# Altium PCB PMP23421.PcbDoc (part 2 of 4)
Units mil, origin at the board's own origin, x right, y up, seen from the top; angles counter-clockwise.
Board outline 2755.91 x 7559.06 mil, 8 copper layers (Top Layer, Signal Layer 1, Signal Layer 2, Signal Layer 3, Signal Layer 4, Signal Layer 5, Signal Layer 6, Bottom Layer), stack 60.4 mil thick; 211 components, 135 nets, 708 pads, 652 vias.
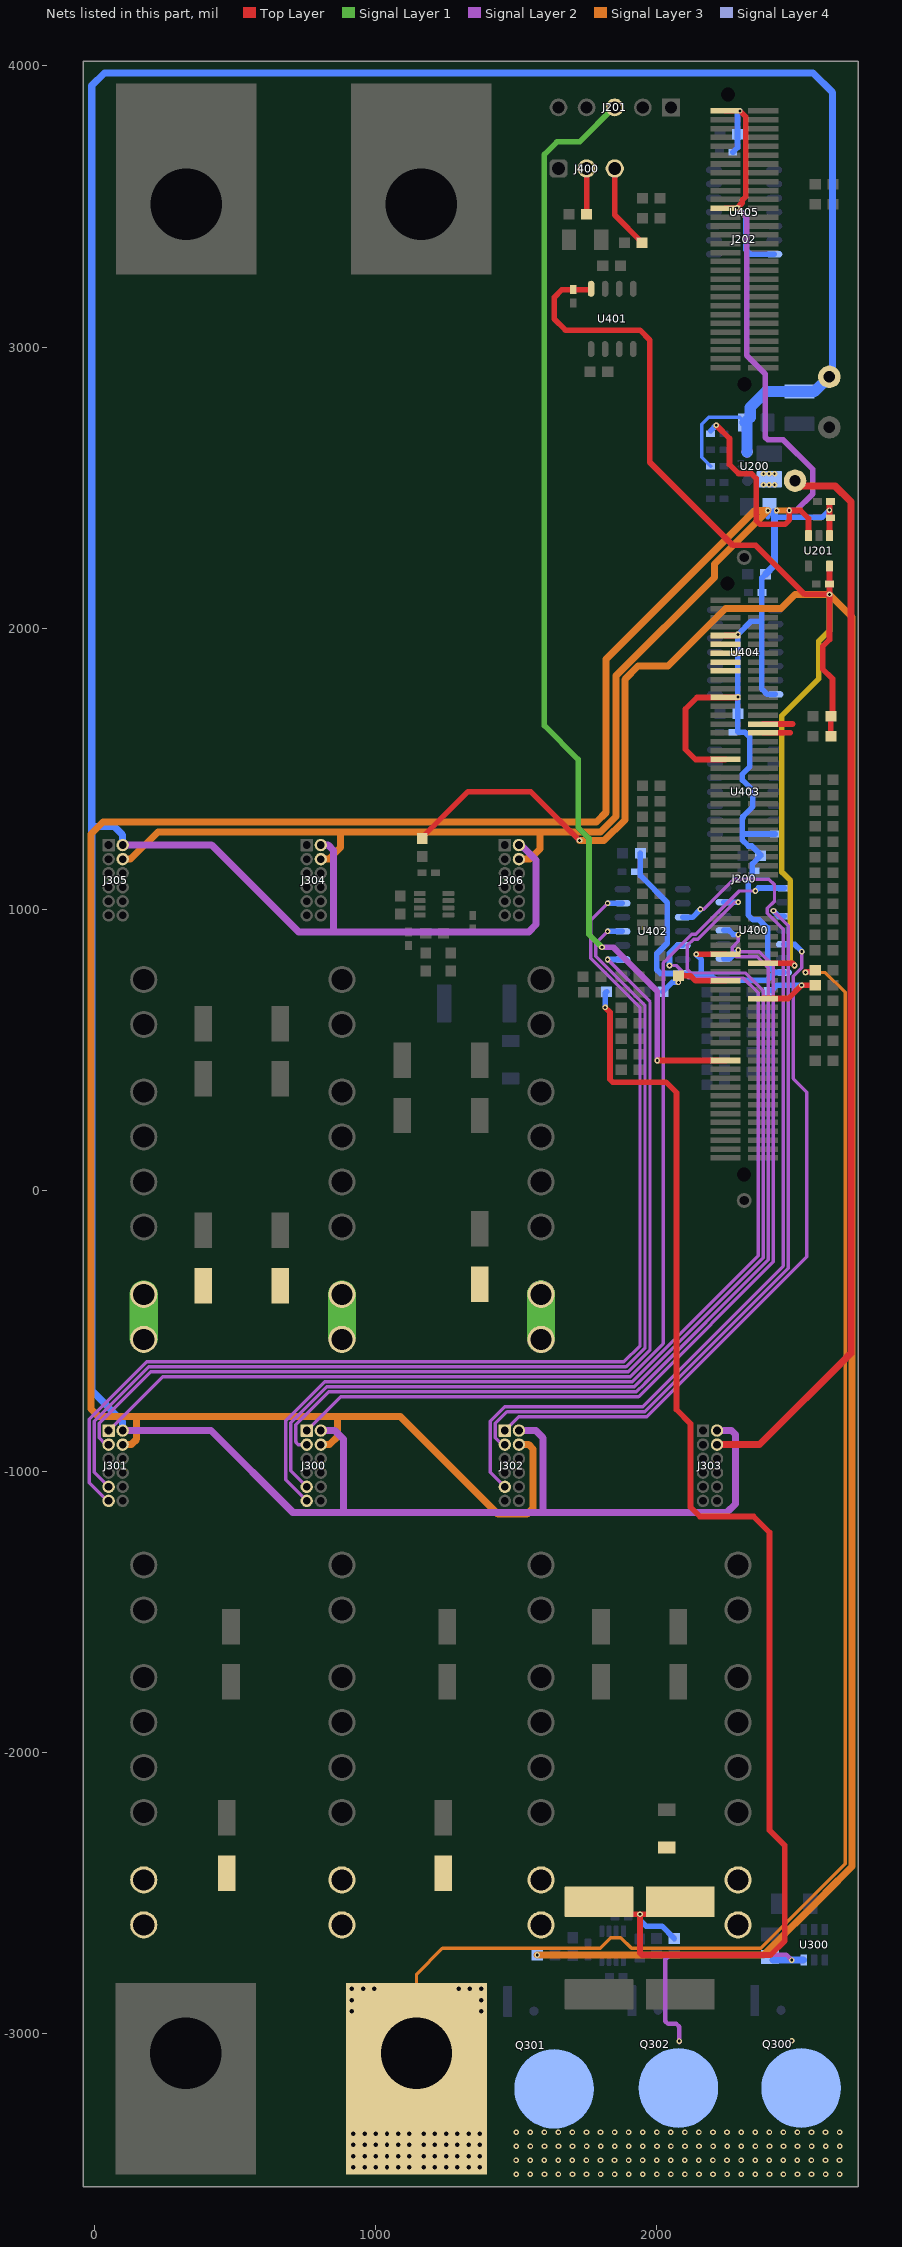
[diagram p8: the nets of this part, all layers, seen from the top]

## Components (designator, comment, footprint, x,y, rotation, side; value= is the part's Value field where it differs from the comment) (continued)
C402 "C1608X7R1C105K080AC" 0603 2337.39,1190.64 r180 bottom value=1uF
C403 "GRM155R70J104KA01D" 0402 2326.28,1137.58 r0 bottom value=0.1uF
C404 "C1608X7R1C105K080AC" 0603 1910,1198.7 r180 bottom value=1uF
C405 "GRM155R70J104KA01D" 0402 1900,1133.99 r0 bottom value=0.1uF
C406 "C1608X7R1C105K080AC" 0603 2257.05,1695.07 r180 bottom value=1uF
C407 "GRM155R70J104KA01D" 0402 2247.05,1630.3 r0 bottom value=0.1uF
C408 "C1608X7R1C105K080AC" 0603 2355,2191.71 r180 bottom value=1uF
C409 "GRM155R70J104KA01D" 0402 2350,2127 r0 bottom value=0.1uF
C410 "C1608X7R1C105K080AC" 0603 2255.56,3757.29 r180 bottom value=1uF
C411 "GRM155R70J104KA01D" 0402 2246.58,3692.58 r0 bottom value=0.1uF
J200 "HSEC8-160-01-L-DV-A-BL" controlCARD-120HSEC 2311.66,1035.21 r90 top locked
J201 "61300511021" Wurth_61300511021 1850.27,3852.41 r180 top
J202 "HSEC8-130-01-L-DV-A" controlCARD-180HSEC-60pinAddon 2311.66,3383.36 r90 top locked
J300 "M50-3000645" FP-M50-3000645_HDR12-MFG 779.72,-979.33 r270 top locked
J301 "M50-3000645" FP-M50-3000645_HDR12-MFG 75,-979.33 r270 top locked
J302 "M50-3000645" FP-M50-3000645_HDR12-MFG 1484.45,-979.33 r270 top locked
J303 "M50-3000645" FP-M50-3000645_HDR12-MFG 2189.17,-979.33 r270 top locked
J304 "M50-3000645" FP-M50-3000645_HDR12-MFG 779.72,1103.35 r270 top locked
J305 "M50-3000645" FP-M50-3000645_HDR12-MFG 75,1103.35 r270 top
J306 "M50-3000645" FP-M50-3000645_HDR12-MFG 1484.45,1103.35 r270 top locked
J400 "61300311121" WURTH_61300311121 1750.27,3635 r0 top
Q300 "IPT010N08NM5ATMA1" FP-IPT010N08NM5ATMA1_HSOF8-MFG 2513.78,-3088.58 r0 bottom
Q301 "IPT010N08NM5ATMA1" FP-IPT010N08NM5ATMA1_HSOF8-MFG 1634.84,-3091.73 r0 bottom
Q302 "IPT010N08NM5ATMA1" FP-IPT010N08NM5ATMA1_HSOF8-MFG 2076.77,-3088.58 r0 bottom
R200 "RC0603JR-070RL" 0603 2595,460.51 r180 top value=0
R201 "CRCW060328K7FKEA" 0603 1769.34,760.67 r180 top value=28.7k
R202 "CRCW060328K7FKEA" 0603 1770.06,705 r180 top value=28.7k
R203 "CRCW060328K7FKEA" 0603 1853.29,707.06 r180 bottom value=28.7k
R204 "CRCW060328K7FKEA" 0603 2595,783.52 r180 top value=28.7k
R205 "RC0603JR-070RL" 0603 2595,532.05 r180 top value=0
R206 "RC0603JR-070RL" 0603 1905,430 r180 top value=0
R207 "RC0603JR-070RL" 0603 1905.51,485 r180 top value=0
R208 "CRCW060328K7FKEA" 0603 1905,760.67 r180 top value=28.7k
R209 "CRCW060328K7FKEA" 0603 1905,705 r180 top value=28.7k
R210 "CRCW060328K7FKEA" 0603 1990.27,707.06 r180 bottom value=28.7k
R211 "CRCW060328K7FKEA" 0603 2595,730 r0 top value=28.7k
R212 "RC0603JR-070RL" 0603 1904.92,595 r180 top value=0
R213 "RC0603JR-070RL" 0603 2595,603.52 r180 top value=0
R214 "CRCW06033K01FKEA" 0603 2210,705.65 r180 bottom value=3.01k
R215 "CRCW06033K01FKEA" 0603 2210,650.65 r180 bottom value=3.01k
R216 "CRCW06033K01FKEA" 0603 2045,763.52 r0 top value=3.01k
R217 "CRCW06033K01FKEA" 0603 2370,705.72 r0 bottom value=3.01k
R218 "RC0603JR-070RL" 0603 2595,675 r180 top value=0
R219 "CRCW040249K9FKED" 0402 2215.07,2576.02 r180 bottom value=49.9k
R220 "RC0402FR-07220KL" 0402 2215.07,2692.04 r180 bottom value=220k
R221 "CRCW040230K0FKED" 0402 2215.07,2634.03 r0 bottom value=30.0k
R222 "CRCW040230K0FKED" 0402 2215.07,2460 r0 bottom value=30.0k
R223 "CRCW06034K75FKEA" 0603 2587.84,1615.72 r0 top value=4.75k
R224 "CRCW06034K75FKEA" 0603 2587.84,1687.2 r0 top value=4.75k
R225 "RC0603JR-070RL" 0603 1606.21,-2720 r0 bottom value=0
R226 "RC0603FR-07100RL" 0603 2030.6,-2661.13 r0 bottom value=100
R227 "RC0603JR-070RL" 0603 1905,540 r0 top value=0
R228 "RC0603FR-07100RL" 0603 2030.6,-2715 r0 bottom value=100
R229 "RC0603JR-070RL" 0603 1165,1220 r270 top value=0
R230 "RC0603FR-07100RL" 0603 1178.11,812.53 r270 top value=100
R231 "RC0603JR-070RL" 0603 1905,650 r0 top value=0
R232 "RC0603FR-07100RL" 0603 1266.69,812.53 r270 top value=100
R300 "CSR2512C0R01F" 2512 1360,665 r0 bottom value=0.01
R301 "PU3921FKNP90U4L" FP-PU3921FKNP90U4L_3921-MFG 2083.34,-2695 r270 top value=400µ
R302 "PU3921FKNP90U4L" FP-PU3921FKNP90U4L_3921-MFG 1794.29,-2695 r270 top value=400µ
R303 "CRCW0805100RDHEAP" 0805_HV 2402.52,-2686.69 r270 bottom value=100
R400 "RCG060310K0FKEA" 0603 2594.9,855 r180 top value=10.0k
R401 "RCG060310K0FKEA" 0603 2594.9,1020 r180 top value=10.0k
R402 "RCG060310K0FKEA" 0603 2594.9,910 r180 top value=10.0k
R403 "RCG060310K0FKEA" 0603 2594.9,1185 r180 top value=10.0k
R404 "RC0603JR-070RL" 0603 1719.13,3473.09 r0 top value=0
R405 "RCG060310K0FKEA" 0603 2594.9,965 r180 top value=10.0k
R406 "RCG060310K0FKEA" 0603 1980,1000 r0 top value=10.0k
R407 "RC0603JR-070RL" 0603 1793.93,2912.57 r0 top value=0
R408 "RC0603FR-07120RL" 0603 1839.21,3289.4 r180 top value=120
R409 "RCG060310K0FKEA" 0603 1980,835 r0 top value=10.0k
R410 "RCG060310K0FKEA" 0603 2594.9,1240 r180 top value=10.0k
R411 "RC0603JR-070RL" 0603 1916.2,3371.66 r0 top value=0
R412 "RCG060310K0FKEA" 0603 2594.9,1075 r180 top value=10.0k
R413 "RCG060310K0FKEA" 0603 1980,945 r0 top value=10.0k
R414 "RCG060310K0FKEA" 0603 2594.9,1130 r180 top value=10.0k
R415 "RCG060310K0FKEA" 0603 1980,890 r0 top value=10.0k
R416 "RCG060310K0FKEA" 0603 1980,1055 r0 top value=10.0k
R417 "RCG060310K0FKEA" 0603 1980,1385 r0 top value=10.0k
R418 "RCG060310K0FKEA" 0603 1980,3458.52 r0 top value=10.0k
R419 "RCG060310K0FKEA" 0603 1980,1110 r0 top value=10.0k
R420 "RCG060310K0FKEA" 0603 1980,1330 r0 top value=10.0k
R421 "RCG060310K0FKEA" 0603 2595,3507.87 r180 top value=10.0k
R422 "RCG060310K0FKEA" 0603 1980,1165 r0 top value=10.0k
R423 "RCG060310K0FKEA" 0603 1980,1275 r0 top value=10.0k
R424 "RCG060310K0FKEA" 0603 1980,3530 r0 top value=10.0k
R425 "RCG060310K0FKEA" 0603 1980,1220 r0 top value=10.0k
R426 "RCG060310K0FKEA" 0603 1980,1440 r0 top value=10.0k
R427 "RCG060310K0FKEA" 0603 2595,3579.35 r180 top value=10.0k
R428 "RCG060310K0FKEA" 0603 2595,1295 r180 top value=10.0k
R429 "RCG060310K0FKEA" 0603 2594.9,1405 r180 top value=10.0k
R430 "RCG060310K0FKEA" 0603 2595,1350 r180 top value=10.0k
R431 "RCG060310K0FKEA" 0603 2595,1460 r180 top value=10.0k
SGND "5001" Keystone5001 2613.78,2714.34 r90 top
T300 "CB70-14-CY" CB70-14-CY 326.77,3507.87 r270 top
T301 "CB70-14-CY" CB70-14-CY 1145.25,-3070 r90 top
T302 "CB70-14-CY" CB70-14-CY 1161.42,3507.87 r270 top
T303 "CB70-14-CY" CB70-14-CY 325,-3070 r90 top
TP300 "Suggest using a net name here" Mill-Max_0312-0-15-15-34-27-10-0 175,-1332.48 r0 top locked
TP301 "Suggest using a net name here" Mill-Max_0312-0-15-15-34-27-10-0 175,-2612.48 r0 top
TP302 "Suggest using a net name here" Mill-Max_0312-0-15-15-34-27-10-0 175,-1892.48 r0 top
TP303 "Suggest using a net name here" Mill-Max_0312-0-15-15-34-27-10-0 879.72,-1332.48 r0 top locked
TP304 "Suggest using a net name here" Mill-Max_0312-0-15-15-34-27-10-0 879.72,-2452.48 r0 top
TP305 "Suggest using a net name here" Mill-Max_0312-0-15-15-34-27-10-0 879.72,-1732.48 r0 top
TP306 "Suggest using a net name here" Mill-Max_0312-0-15-15-34-27-10-0 1588.45,-1332.48 r0 top locked
TP307 "Suggest using a net name here" Mill-Max_0312-0-15-15-34-27-10-0 1588.45,-2612.48 r0 top
TP308 "Suggest using a net name here" Mill-Max_0312-0-15-15-34-27-10-0 1588.45,-1732.48 r0 top
TP309 "Suggest using a net name here" Mill-Max_0312-0-15-15-34-27-10-0 175,-1492.48 r0 top locked
TP310 "Suggest using a net name here" Mill-Max_0312-0-15-15-34-27-10-0 175,-2452.48 r0 top
TP311 "Suggest using a net name here" Mill-Max_0312-0-15-15-34-27-10-0 175,-1732.48 r0 top
TP312 "Suggest using a net name here" Mill-Max_0312-0-15-15-34-27-10-0 879.72,-1492.48 r0 top locked
TP313 "Suggest using a net name here" Mill-Max_0312-0-15-15-34-27-10-0 879.72,-2612.48 r0 top
TP314 "Suggest using a net name here" Mill-Max_0312-0-15-15-34-27-10-0 879.72,-2212.48 r0 top
TP315 "Suggest using a net name here" Mill-Max_0312-0-15-15-34-27-10-0 1588.45,-1492.48 r0 top locked
TP316 "Suggest using a net name here" Mill-Max_0312-0-15-15-34-27-10-0 1588.45,-2452.48 r0 top
TP317 "Suggest using a net name here" Mill-Max_0312-0-15-15-34-27-10-0 1588.45,-2212.48 r0 top
TP318 "Suggest using a net name here" Mill-Max_0312-0-15-15-34-27-10-0 175,-2052.48 r0 top
TP319 "Suggest using a net name here" Mill-Max_0312-0-15-15-34-27-10-0 879.72,-1892.48 r0 top
TP320 "Suggest using a net name here" Mill-Max_0312-0-15-15-34-27-10-0 1588.45,-1892.48 r0 top
TP321 "Suggest using a net name here" Mill-Max_0312-0-15-15-34-27-10-0 175,-2212.48 r0 top
TP322 "Suggest using a net name here" Mill-Max_0312-0-15-15-34-27-10-0 879.72,-2052.48 r0 top
TP323 "Suggest using a net name here" Mill-Max_0312-0-15-15-34-27-10-0 1588.45,-2052.48 r0 top
TP324 "Suggest using a net name here" Mill-Max_0312-0-15-15-34-27-10-0 2289.17,-1332.48 r0 top locked
TP325 "Suggest using a net name here" Mill-Max_0312-0-15-15-34-27-10-0 2289.17,-2612.48 r0 top locked
TP326 "Suggest using a net name here" Mill-Max_0312-0-15-15-34-27-10-0 2289.17,-1732.48 r0 top locked
TP327 "Suggest using a net name here" Mill-Max_0312-0-15-15-34-27-10-0 175,590.2 r0 top locked
TP328 "Suggest using a net name here" Mill-Max_0312-0-15-15-34-27-10-0 175,-529.8 r0 top locked
TP329 "Suggest using a net name here" Mill-Max_0312-0-15-15-34-27-10-0 1588.45,350.2 r0 top locked
TP330 "Suggest using a net name here" Mill-Max_0312-0-15-15-34-27-10-0 879.72,750.2 r0 top
TP331 "Suggest using a net name here" Mill-Max_0312-0-15-15-34-27-10-0 879.72,-529.8 r0 top
TP332 "Suggest using a net name here" Mill-Max_0312-0-15-15-34-27-10-0 879.72,350.2 r0 top
TP333 "Suggest using a net name here" Mill-Max_0312-0-15-15-34-27-10-0 1588.45,590.2 r0 top
TP334 "Suggest using a net name here" Mill-Max_0312-0-15-15-34-27-10-0 1588.45,-529.8 r0 top
TP335 "Suggest using a net name here" Mill-Max_0312-0-15-15-34-27-10-0 175,30.2 r0 top
TP336 "Suggest using a net name here" Mill-Max_0312-0-15-15-34-27-10-0 2289.17,-1492.48 r0 top locked
TP337 "Suggest using a net name here" Mill-Max_0312-0-15-15-34-27-10-0 2289.17,-2452.48 r0 top locked
TP338 "Suggest using a net name here" Mill-Max_0312-0-15-15-34-27-10-0 2289.17,-1892.48 r0 top locked
TP339 "Suggest using a net name here" Mill-Max_0312-0-15-15-34-27-10-0 175,750.2 r0 top locked
TP340 "Suggest using a net name here" Mill-Max_0312-0-15-15-34-27-10-0 175,-369.8 r0 top locked
TP341 "Suggest using a net name here" Mill-Max_0312-0-15-15-34-27-10-0 1588.45,190.2 r0 top locked
TP342 "Suggest using a net name here" Mill-Max_0312-0-15-15-34-27-10-0 879.72,590.2 r0 top
TP343 "Suggest using a net name here" Mill-Max_0312-0-15-15-34-27-10-0 879.72,-369.8 r0 top
TP344 "Suggest using a net name here" Mill-Max_0312-0-15-15-34-27-10-0 879.72,190.2 r0 top
TP345 "Suggest using a net name here" Mill-Max_0312-0-15-15-34-27-10-0 1588.45,750.2 r0 top
TP346 "Suggest using a net name here" Mill-Max_0312-0-15-15-34-27-10-0 1588.45,-369.8 r0 top
TP347 "Suggest using a net name here" Mill-Max_0312-0-15-15-34-27-10-0 175,350.2 r0 top
TP348 "Suggest using a net name here" Mill-Max_0312-0-15-15-34-27-10-0 2289.17,-2052.48 r0 top locked
TP349 "Suggest using a net name here" Mill-Max_0312-0-15-15-34-27-10-0 1588.45,30.2 r0 top locked
TP350 "Suggest using a net name here" Mill-Max_0312-0-15-15-34-27-10-0 879.72,-129.8 r0 top
TP351 "Suggest using a net name here" Mill-Max_0312-0-15-15-34-27-10-0 175,-129.8 r0 top
TP352 "Suggest using a net name here" Mill-Max_0312-0-15-15-34-27-10-0 2289.17,-2212.48 r0 top locked
TP353 "Suggest using a net name here" Mill-Max_0312-0-15-15-34-27-10-0 1588.45,-129.8 r0 top locked
TP354 "Suggest using a net name here" Mill-Max_0312-0-15-15-34-27-10-0 879.72,30.2 r0 top
TP355 "Suggest using a net name here" Mill-Max_0312-0-15-15-34-27-10-0 175,190.2 r0 top
U200 "TPSM863252RDX" RDX0007A-MFG 2373.03,2574.97 r270 bottom
U201 "TLV71333PQDBVRQ1" DBV0005A_N 2576.82,2275 r270 top
U202 "INA296A4IDDF" DDF0008A-MFG 1842.7,-2686.42 r90 bottom
U203 "INA296A3IDDF" DDF0008A-MFG 1207.64,1017.8 r180 top
U300 "LM5050MK-1/NOPB" DDC0006A_N 2560,-2683.77 r270 bottom
U400 "SN74ALS1034D" D0014A_L 2345,925 r0 bottom
U401 "THVD1450D" D0008A_N 1841.18,3100 r90 top
U402 "SN74ALS1034D" D0014A_L 1985,921.41 r0 bottom
U403 "SN74ALS1034D" D0014A_L 2314.41,1417.72 r0 bottom
U404 "SN74ALS1034D" D0014A_L 2314.42,1914.42 r0 bottom
U405 "SN74ALS1034D" D0014A_L 2310.56,3480 r0 bottom

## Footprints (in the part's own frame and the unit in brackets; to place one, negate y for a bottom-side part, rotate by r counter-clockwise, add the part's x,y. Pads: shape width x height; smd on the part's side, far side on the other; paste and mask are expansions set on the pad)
0402 [mm] "0402 from SM-752 data"
  rect 0.8x0.6 smd: 1(-0.6,0) 2(0.6,0)
  silkscreen extent -1.22,-0.52 1.22,0.52, body extent -0.55,-0.3 0.55,0.3, height 0.6
0603 [mm] "0603 from SM-752 data"
  rect 1x0.95 smd: 1(-0.8,0) 2(0.8,0)
  silkscreen extent -1.52,-0.69 1.52,0.69, body extent -0.87,-0.47 0.87,0.47, height 1
0805_HV [mil] "0805 with 30mil clearance between pads"
  rect 50x63 smd: 1(-40,0) 2(40,0)
  silkscreen extent -74,-40 74,40, body extent -43,-29 43,29, height 57
1206 [mm] "1206 from SM-752 data"
  rect 1.3x1.85 smd: 1(-1.45,0) 2(1.45,0)
  silkscreen extent -2.4,-1.21 2.4,1.21, body extent -1.7,-0.9 1.7,0.9, height 1.35
1206_180 [mm] "1206_180"
  rect 1.1x1.6 smd: 1(-1.7,0) 2(1.7,0)
  silkscreen extent -0.9,-1 0.9,1, body extent -1.75,-0.95 1.75,0.95, height 1.8
1210_270 [mm] "1210"
  rect 1.3x2.7 smd: 1(-1.45,0) 2(1.45,0)
  silkscreen extent -2.32,-1.57 2.32,1.57, body extent -1.7,-1.35 1.7,1.35, height 2.7
2512 [mm] "Chip Resistor, Body 6.3x3.2mm, IPC Medium Density"
  rect 1.3x3.4 smd: 1(-2.95,0) 2(2.95,0)
  silkscreen extent -1.9,-1.6 1.9,1.6, body extent -3.22,-1.67 3.22,1.67, height 0.71
CB70-14-CY [mil] "Terminal 90A Lug"
  rect 680x500 hole 254 copper offset -90,0 paste-250: 1(0,0)
  body extent -1300,-260 250,260, height 714
controlCARD-120HSEC [mm] "Pads are not numbered according to Samtec datasheet."
  rect 0.5x2.724 smd: 1(-23.357,-1.678) 2(-23.357,1.722) 3(-22.557,-1.678) 4(-22.557,1.722) 5(-21.757,-1.678) 6(-21.757,1.722) 7(-20.957,-1.678) 8(-20.957,1.722) 9(-20.157,-1.678) 10(-20.157,1.722) 11(-19.357,-1.678) 12(-19.357,1.722) 13(-18.557,-1.678) 14(-18.557,1.722) 15(-17.757,-1.678) 16(-17.757,1.722) 17(-16.957,-1.678) 18(-16.957,1.722) 19(-16.157,-1.678) 20(-16.157,1.722) 21(-15.357,-1.678) 22(-15.357,1.722) 23(-14.557,-1.678) 24(-14.557,1.722) 25(-13.757,-1.678) 26(-13.757,1.722) 27(-12.957,-1.678) 28(-12.957,1.722) 29(-12.157,-1.678) 30(-12.157,1.722) 31(-11.357,-1.678) 32(-11.357,1.722) 33(-10.557,-1.678) 34(-10.557,1.722) 35(-9.757,-1.678) 36(-9.757,1.722) 37(-8.957,-1.678) 38(-8.957,1.722) 39(-8.157,-1.678) 40(-8.157,1.722) 41(-7.357,-1.678) 42(-7.357,1.722) 43(-6.557,-1.678) 44(-6.557,1.722) 45(-5.757,-1.678) 46(-5.757,1.722) 47(-4.957,-1.678) 48(-4.957,1.722) 49(-4.157,-1.678) 50(-4.157,1.722) 51(-3.357,-1.678) 52(-3.357,1.722) 53(-2.557,-1.678) 54(-2.557,1.722) 55(-1.757,-1.678) 56(-1.757,1.722) 57(2.243,-1.678) 58(2.243,1.722) 59(3.043,-1.678) 60(3.043,1.722) 61(3.843,-1.678) 62(3.843,1.722) 63(4.643,-1.678) 64(4.643,1.722) 65(5.443,-1.678) 66(5.443,1.722) 67(6.243,-1.678) 68(6.243,1.722) 69(7.043,-1.678) 70(7.043,1.722) 71(7.843,-1.678) 72(7.843,1.722) 73(8.643,-1.678) 74(8.643,1.722) 75(9.443,-1.678) 76(9.443,1.722) 77(10.243,-1.678) 78(10.243,1.722) 79(11.043,-1.678) 80(11.043,1.722) 81(11.843,-1.678) 82(11.843,1.722) 83(12.643,-1.678) 84(12.643,1.722) 85(13.443,-1.678) 86(13.443,1.722) 87(14.243,-1.678) 88(14.243,1.722) 89(15.043,-1.678) 90(15.043,1.722) 91(15.843,-1.678) 92(15.843,1.722) 93(16.643,-1.678) 94(16.643,1.722) 95(17.443,-1.678) 96(17.443,1.722) 97(18.243,-1.678) 98(18.243,1.722) 99(19.043,-1.678) 100(19.043,1.722) 101(19.843,-1.678) 102(19.843,1.722) 103(20.643,-1.678) 104(20.643,1.722) 105(21.443,-1.678) 106(21.443,1.722) 107(22.243,-1.678) 108(22.243,1.722) 109(23.043,-1.678) 110(23.043,1.722) 111(23.843,-1.678) 112(23.843,1.722) 113(24.643,-1.678) 114(24.643,1.722) 115(25.443,-1.678) 116(25.443,1.722) 117(26.243,-1.678) 118(26.243,1.722) 119(27.043,-1.678) 120(27.043,1.722)
  round 0.025 hole 1.27 unplated mask+0.876: 181(-24.857,0.022) 182(28.543,1.522)
  round 1.348 hole 0.84: 185(-27.207,0.022) 186(30.893,0.022)
  silkscreen extent -32.11,-3.86 35.8,3.9, body extent -31.75,-3.48 35.3,3.52, height 12.35
controlCARD-180HSEC-60pinAddon [mm] "Pads are not numbered according to datasheet."
  round 0.025 hole 1.27 unplated mask+0.876: 61(-13.1,0) 62(13.1,1.5)
  rect 0.5x2.724 smd: 121(-11.6,-1.7) 122(-11.6,1.7) 123(-10.8,-1.7) 124(-10.8,1.7) 125(-10,-1.7) 126(-10,1.7) 127(-9.2,-1.7) 128(-9.2,1.7) 129(-8.4,-1.7) 130(-8.4,1.7) 131(-7.6,-1.7) 132(-7.6,1.7) 133(-6.8,-1.7) 134(-6.8,1.7) 135(-6,-1.7) 136(-6,1.7) 137(-5.2,-1.7) 138(-5.2,1.7) 139(-4.4,-1.7) 140(-4.4,1.7) 141(-3.6,-1.7) 142(-3.6,1.7) 143(-2.8,-1.7) 144(-2.8,1.7) 145(-2,-1.7) 146(-2,1.7) 147(-1.2,-1.7) 148(-1.2,1.7) 149(-0.4,-1.7) 150(-0.4,1.7) 151(0.4,-1.7) 152(0.4,1.7) 153(1.2,-1.7) 154(1.2,1.7) 155(2,-1.7) 156(2,1.7) 157(2.8,-1.7) 158(2.8,1.7) 159(3.6,-1.7) 160(3.6,1.7) 161(4.4,-1.7) 162(4.4,1.7) 163(5.2,-1.7) 164(5.2,1.7) 165(6,-1.7) 166(6,1.7) 167(6.8,-1.7) 168(6.8,1.7) 169(7.6,-1.7) 170(7.6,1.7) 171(8.4,-1.7) 172(8.4,1.7) 173(9.2,-1.7) 174(9.2,1.7) 175(10,-1.7) 176(10,1.7) 177(10.8,-1.7) 178(10.8,1.7) 179(11.6,-1.7) 180(11.6,1.7)
  silkscreen extent -14.68,-3.88 14.68,3.88, body extent -14.3,-3.5 14.3,3.5, height 7.95
D0008A_N [mm] "SOIC, 8-Leads, Body 4.9x3.9mm, Pitch 1.27mm, IPC Medium Density"
  oval 1.45x0.6 smd: 1(-2.725,1.905) 2(-2.725,0.635) 3(-2.725,-0.635) 4(-2.725,-1.905) 5(2.725,-1.905) 6(2.725,-0.635) 7(2.725,0.635) 8(2.725,1.905)
  silkscreen extent -3.3,-2.5 0.9,2.5, body extent -3,-2.45 3,2.45, height 1.63
D0014A_L [mm] "SOIC, 14-Leads, Body 8.7x3.9mm, Pitch 1.27mm, IPC High Density"
  oval 1.45x0.6 smd: 1(-2.725,3.81) 2(-2.725,2.54) 3(-2.725,1.27) 4(-2.725,0) 5(-2.725,-1.27) 6(-2.725,-2.54) 7(-2.725,-3.81) 8(2.725,-3.81) 9(2.725,-2.54) 10(2.725,-1.27) 11(2.725,0) 12(2.725,1.27) 13(2.725,2.54) 14(2.725,3.81)
  silkscreen extent -3.3,-4.4 0.9,4.4, body extent -3.02,-4.32 3.02,4.32, height 1.6
DBV0005A_N [mm] "SOT23, 5-Leads, Body 2.9x1.6mm, Pitch 0.95mm, Lead Span 2.8mm, IPC Medium Density"
  rrect17% 1x0.6 smd: 1(-1.375,0.95) 2(-1.375,0) 3(-1.375,-0.95) 4(1.375,-0.95) 5(1.375,0.95)
  silkscreen extent -1.63,-1.55 0.38,1.55, body extent -1.42,-1.46 1.42,1.46, height 1.09
DDC0006A_N [mm]
  rrect17% 1x0.6 smd: 1(-1.375,0.95) 2(-1.375,0) 3(-1.375,-0.95) 4(1.375,-0.95) 5(1.375,0) 6(1.375,0.95)
  silkscreen extent -1.75,-1.52 0.7,1.53, body extent -1.43,-1.48 1.43,1.49, height 0.92
DDF0008A-MFG [mm]
  rrect22% 1.05x0.45 smd paste+0 mask+0: 1(-1.3,0.975) 2(-1.3,0.325) 3(-1.3,-0.325) 4(-1.3,-0.975) 5(1.3,-0.975) 6(1.3,-0.325) 7(1.3,0.325) 8(1.3,0.975)
  silkscreen extent -2.01,-1.48 0.4,1.67, body extent -1.41,-1.45 1.41,1.45, height 1.1
FP-IPT010N08NM5ATMA1_HSOF8-MFG [mm]
  rrect13% 0.8x2.8 smd paste-1000 mask+0: 1(-4.2,-5.25)
  round 0.837 smd paste-1000 mask+0: 2-3-4-5-6-7-8(-1.825,-4.375)
  round 7.2 smd paste-1000 mask+0: 9(0,2.65)
  Top Layer region: 4.6,-6.65 4.6,-3.85 -3.4,-3.85 -3.4,-6.65 -2.6,-6.65 -2.6,-4.65 -2.2,-4.65 -2.2,-6.65 -1.4,-6.65 -1.4,-4.65 -1,-4.65 -1,-6.65 -0.2,-6.65 -0.2,-4.65 0.2,-4.65 0.2,-6.65 1,-6.65 1,-4.65 1.4,-4.65 1.4,-6.65 2.2,-6.65 2.2,-4.65 2.6,-4.65 2.6,-6.65 3.4,-6.65 3.4,-4.65 3.8,-4.65 3.8,-6.65 4.6,-6.65
  Top Layer region: -5.05,6.65 5.05,6.65 5.05,5.25 4.35,5.25 4.35,2.35 5.05,2.35 5.05,-1.35 -5.05,-1.35 -5.05,2.35 -4.35,2.35 -4.35,5.25 -5.05,5.25 -5.05,6.65
  silkscreen extent -5.05,-7.32 5.05,-1.73, body extent -4.95,-5.84 4.95,5.84, height 2.4
FP-M50-3000645_HDR12-MFG [mm]
  rrect9% 1.12x1.12 hole 0.7 paste-1000 mask+0: 1(-3.175,-0.635)
  round 1.12 hole 0.7 paste-1000 mask+0: 2(-3.175,0.635) 3(-1.905,-0.635) 4(-1.905,0.635) 5(-0.635,-0.635) 6(-0.635,0.635) 7(0.635,-0.635) 8(0.635,0.635) 9(1.905,-0.635) 10(1.905,0.635) 11(3.175,-0.635) 12(3.175,0.635)
  silkscreen extent -4.73,-1.63 4.16,1.63, body extent -4.26,-1.73 4.26,1.73, height 0.25
FP-PU3921FKNP90U4L_3921-MFG [mm]
  rrect4% 2.75x6.2 smd paste+0 mask+0: 1(-4.175,0) 2(4.175,0)
  silkscreen extent -2.42,-2.73 2.42,2.73, body extent -5,-2.6 5,2.6, height 1.81
Keystone5000 [mil] "For Keystone 500x miniature loop terminals"
  round 80 hole 40: 1(0,0)
  silkscreen extent -52,-52 52,52, body extent -49,-49 49,49, height 182
Keystone5001 [mil] "For Keystone 500x miniature loop terminals"
  round 80 hole 40: 1(0,0)
  silkscreen extent -52,-52 52,52, body extent -49,-49 49,49, height 182
Mill-Max_0312-0-15-15-34-27-10-0 [mm] "Pin Receptacle, .032-.046\" .075\" Dia, Gold, TH"
  round 2.45 hole 1.905: 1(0,0)
  silkscreen extent -1.52,-1.52 1.52,1.52, body extent -1.15,-1.15 1.16,1.15, height 0.46
RDX0007A-MFG [mm]
  round 1.025 smd paste-1000 mask-1000: 1(-1.312,1.312)
  rrect13% 1.5x2.3 smd paste-1000 mask-1000: 2(-1.15,-0.675) 3(1.15,-0.675)
  round 0.991 smd paste-1000 mask-1000: 4(1.281,1.276)
  rrect45% 0.22x0.6 smd paste+0 mask-1000: 5(0.5,1.9) 6(0,1.9) 7(-0.5,1.9)
  Top Layer region: 1.9,1.8 1.892,1.838 1.871,1.871 1.838,1.892 1.8,1.9 1.8,1.9 0.925,1.9 0.887,1.892 0.854,1.871 0.833,1.838 0.825,1.8 0.825,1.8 0.825,1.634 0.818,1.596 0.796,1.563 0.796,1.563 0.507,1.274 0.474,1.252 0.436,1.245 0.436,1.245 0.39,1.245 0.352,1.237 0.319,1.216 0.298,1.183 0.29,1.145 0.29,1.145 0.29,0.825 0.298,0.787 0.319,0.754 0.352,0.733 0.39,0.725 0.39,0.725 1.8,0.725 1.838,0.733 1.871,0.754 1.892,0.787 1.9,0.825 1.9,0.825
  Top Layer region: -1.9,1.8 -1.887,1.85 -1.85,1.887 -1.8,1.9 -1.8,1.9 -0.925,1.9 -0.887,1.892 -0.854,1.871 -0.833,1.838 -0.825,1.8 -0.825,1.8 -0.825,1.634 -0.818,1.596 -0.796,1.563 -0.796,1.563 -0.507,1.274 -0.474,1.252 -0.436,1.245 -0.436,1.245 -0.39,1.245 -0.34,1.232 -0.303,1.195 -0.29,1.145 -0.29,1.145 -0.29,0.825 -0.298,0.787 -0.319,0.754 -0.352,0.733 -0.39,0.725 -0.39,0.725 -1.8,0.725 -1.838,0.733 -1.871,0.754 -1.892,0.787 -1.9,0.825 -1.9,0.825
  Keep-Out Layer region: -0.2,1.295 0.2,1.295 0.2,0.675 -0.2,0.675
  silkscreen extent -2.52,-2.17 2.07,2.37, body extent -1.65,-2 1.65,2, height 2.1
SM_RADIAL_D [mm] "6.3 x 5.8mm:  Panasonic D"
  rect 3.2x1.6 smd: 1(-2.5,0) 2(2.5,0)
  silkscreen extent -3.4,-3.4 3.4,3.4, body extent -3.4,-3.4 3.4,3.4, height 6.1
WURTH_61300311121 [mm] "Header, 2.54mm, 3x1, TH"
  rrect50% 1.65x1.65 hole 1.15: 1(-2.54,0)
  round 1.65 hole 1.15: 2(0,0) 3(2.54,0)
  body extent -3.81,-1.27 3.81,1.27, height 8.54
Wurth_61300511021 [mm] "Header, 2.54 mm, 5x1, R/A, TH"
  rect 1.6x1.6 hole 1.1: 1(-5.08,0)
  round 1.6 hole 1.1: 2(-2.54,0) 3(0,0) 4(2.54,0) 5(5.08,0)
  silkscreen extent -6.75,-4.04 6.35,-1.5, body extent -6.35,-10.04 6.35,0.32, height 2.55

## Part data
5V 12Vs: "Test Point, Miniature, Red, TH", Color=Red, Manufacturer=Keystone, Supplier Part Number 1=36-5000-ND
C200 C201 C202 C203 C204 C205 C206 C219 C225: "CAP, CERM, 10 pF, 50 V,+/- 1%, C0G/NP0, 0603", Cap_Case=0603, Manufacturer=Kemet, Supplier Part Number 1=399-9958-1-ND, TempCo=C0G/NP0, Tolerance_%=1, Value2=50V, ValueDisplayed=10pF
C207: library part CMP-0009211-2, "CAP, CERM, 47 uF, 16 V, +/- 10%, X5R, 1210", Cap_Case=1210, Manufacturer=MuRata, Supplier Part Number 1=GRM32ER61C476KE15L-ND, TempCo=X5R, Tolerance_%=10%, Value1=Unknown, Value2=16V, ValueDisplayed=47uF
C208: library part CMP-0007728-2, "CAP, CERM, 1 uF, 25 V, +/- 10%, X7R, 0805", Cap_Case=0805, Manufacturer=Kemet, Supplier Part Number 1=399-8004-1-ND, TempCo=X7R, Tolerance_%=10%, Value1=Unknown, Value2=25V, ValueDisplayed=1uF
C209: library part CMP-0007989-2, "CAP, CERM, 22 uF, 6.3 V, +/- 10%, X5R, 0805", Cap_Case=0805, Manufacturer="Samsung Electro-Mechanics", TempCo=X5R, Tolerance_%=10%, Value1=Unknown, Value2=6.3V, ValueDisplayed=22uF
C210 C212 C213 C218 C224 C400 C403 C405 C407 C409 C411: "CAP, CERM, 0.1uF, 6.3V, +/-10%, X7R, 0402", Cap_Case=0402, Manufacturer=MuRata, Supplier Part Number 1=GRM155R70J104KA01D-ND, TempCo=X7R, Tolerance_%=10, Value1=Unknown, Value2=6.3V, ValueDisplayed=0.1uF
C211: library part CMP-0078218-1, "CAP, CERM, 0.01 µF, 16 V,+/- 10%, X7R, 0402", Cap_Case=0402, Manufacturer=Kemet, Supplier Part Number 1=399-1038-1-ND, TempCo=X7R, Tolerance_%=10%, Value2=16V, ValueDisplayed=0.01µF
C214 C220: "CAP, CERM, 68 pF, 50 V,+/- 5%, C0G/NP0, 0603", Cap_Case=0603, Manufacturer=AVX, Supplier Part Number 1=478-1173-1-ND, TempCo=C0G/NP0, Tolerance_%=5, Value1="0.144 ohm", Value2=50V, ValueDisplayed=68pF
C215 C216 C221 C222: "CAP, CERM, 47 pF, 50 V,+/- 1%, C0G/NP0, 0402", Cap_Case=0402, Manufacturer=MuRata, Supplier Part Number 1=490-6241-1-ND, TempCo=C0G/NP0, Tolerance_%=1, Value2=50V, ValueDisplayed=47pF
C217 C223 C402 C404 C406 C408 C410: "CAP, CERM, 1 µF, 16 V,+/- 10%, X7R, 0603", Cap_Case=0603, Manufacturer=TDK, Supplier Part Number 1=445-1604-1-ND, TempCo=X7R, Tolerance_%=10, Value1="0.0057 ohm", Value2=16V, ValueDisplayed=1µF
C300 C313: library part C3216X6S1H475K160AB, "CAP CER 4.7UF 100V X7S 1206", Cap_Case=1206, TempCo=X7S, Tolerance_%=10, Value2=100V, ValueDisplayed=4.7µF
C301 C302 C303 C304 C305 C306 C307 C308 C309 C310 C311 C312 C315: library part EEE-FK1H220P, "CAP ALUM POLY HYB 22UF 63V SMD", Cap_Case=D, Manufacturer=Rubycon, Tolerance_%=20, Value1="0.88 ohm", Value2=63V, ValueDisplayed=22µF
C314 C401: "CAP, CERM, 0.1 µF, 100 V,+/- 5%, X7R, 1206", Cap_Case=1206, Manufacturer=AVX, Supplier Part Number 1=478-3785-1-ND, TempCo=X7R, Tolerance_%=5, Value1="0.037 ohm", Value2=100V, ValueDisplayed=0.1µF
J200: library part CMP-0003814-2, "C2000 controlCARD-120HSEC connector, SMT", Manufacturer=Samtec
J201: library part CMP-0054800-1, "Header, 2.54 mm, 5x1, Gold, R/A, TH", Color=Black, Manufacturer="Wurth Elektronik", Supplier Part Number 1=732-5338-ND
J202: library part CMP-0003859-2, "C2000 controlCARD-180HSEC (60-pin addon) connector, SMT", Manufacturer=Samtec
J300 J301 J302 J303 J304 J305 J306: library part CMP-0094055-1, "12 Position Receptacle Connector 0.050\" (1.27mm) Through Hole Gold", Current_A=1A, Digikey Part Number=952-1366-5-ND, Manufacturer=Harwin, Mouser Part Number=855-M50-3000645, Operating Temperature Range="-40°C to +105°C"
J400: library part CMP-0054796-4, "Header, 2.54 mm, 3x1, Gold, TH", Manufacturer="Wurth Elektronik", Supplier Part Number 1=732-5316-ND
Q300 Q301 Q302: library part CMP-0120006-1, "Transistor Power MOSFET N-Channel 80V 425A 8-Pin HSOF T/R", Digikey Part Number=448-IPT010N08NM5ATMA1CT-ND, Drain To Source Breakdown Voltage=80V, Input Capacitace At Vds="12000pF @ 40V", Manufacturer=Infineon, Mouser Part Number=726-IPT010N08NM5ATM1, Operating Temperature Range="-55°C to +175°C", Power_W=3.8W, Pulse Drain Current=1700A, Typ Forward Diode Voltage=0.87V
R200 R205 R206 R207 R212 R213 R218 R225 R227 R229 R231 R404 R407 R411: "RES, 0, 5%, 0.1 W, 0603", Manufacturer="Yageo America", Power_W=0.1, Supplier Part Number 1=311-0.0GRCT-ND, TempCo="200 ppm/C", Tolerance_%=5, Value1=5%, Value2=0.1W, Value_Code=0000, ValueDisplayed=0
R201 R202 R203 R204 R208 R209 R210 R211: "RES, 28.7 k, 1%, 0.1 W, 0603", Manufacturer=Vishay-Dale, Power_W=0.1, Supplier Part Number 1=541-28.7KHCT-ND, TempCo="100 ppm/C", Tolerance_%=1, Value1=1%, Value2=0.1W, Value_Code=28k7, ValueDisplayed=28.7k
R214 R215 R216 R217: "RES, 3.01 k, 1%, 0.1 W, 0603", Manufacturer=Vishay-Dale, Power_W=0.1, Supplier Part Number 1=541-3.01KHCT-ND, TempCo="100 ppm/C", Tolerance_%=1, Value1=1%, Value2=0.1W, Value_Code=3k01, ValueDisplayed=3.01k
R219: library part CMP-0026403-2, "RES, 49.9 k, 1%, 0.063 W, AEC-Q200 Grade 0, 0402", Manufacturer=Vishay-Dale, Power_W=63mW, Supplier Part Number 1=541-49.9KLCT-ND, TempCo="100 ppm/C", Tolerance_%=1%, Value2=0.063W, Value_Code=49k9, ValueDisplayed=49.9k
R220: library part CMP-0026728-1, "RES, 220 k, 1%, 0.0625 W, 0402", Manufacturer="Yageo America", Power_W=62.5mW, Supplier Part Number 1=311-220KLRCT-ND, TempCo="100 ppm/C", Tolerance_%=1%, Value2=0.0625W, Value_Code=220k
R221 R222: library part CMP-0078244-2, "RES, 30.0 k, 1%, 0.063 W, AEC-Q200 Grade 0, 0402", Manufacturer=Vishay-Dale, Power_W=63mW, Supplier Part Number 1=541-30.0KLCT-ND, TempCo="100 ppm/C", Tolerance_%=1%, Value2=0.063W, Value_Code=30k0, ValueDisplayed=30.0k
R223 R224: "RES, 4.75 k, 1%, 0.1 W, 0603", Manufacturer=Vishay-Dale, Power_W=0.1, Supplier Part Number 1=541-4.75KHCT-ND, TempCo="100 ppm/C", Tolerance_%=1, Value1=1%, Value2=0.1W, Value_Code=4k75, ValueDisplayed=4.75k
R226 R228 R230 R232: "RES, 100, 1%, 0.1 W, 0603", Manufacturer="Yageo America", Power_W=0.1, Supplier Part Number 1=311-100HRCT-ND, TempCo="200 ppm/C", Tolerance_%=1, Value1=1%, Value2=0.1W, Value_Code=100R, ValueDisplayed=100
R300: "RES, 0.01, 1%, 3 W, AEC-Q200 Grade 0, 2512", Manufacturer=Riedon, Power_W=3, Supplier Part Number 1=696-1672-1-ND, TempCo="75 ppm/C", Tolerance_%=1, Value1=1%, Value2=3W, Value_Code=R010, ValueDisplayed=0.01
R301 R302: library part CMP-0096319-1, "400 µOhms ±1% 9W Chip Resistor Nonstandard Automotive AEC-Q200, Current Sense, Moisture Resistant Metal Element", Digikey Part Number=YAG6132CT-ND, Manufacturer=YAGEO, Mouser Part Number=603-PU3921FKNP90U4L, Operating Temperature Range="-65°C to +170°C", Power_W=9W, TempCo=175ppm/°C, Tolerance_%=1%
R303: "RES, 100, 0.5%, 0.125 W, AEC-Q200 Grade 0, 0805", Manufacturer=Vishay-Dale, Power_W=0.125, Supplier Part Number 1=541-100AZCT-ND, TempCo="50 ppm/C", Tolerance_%=0.5, Value1=0.5%, Value2=0.125W, Value_Code=100R, ValueDisplayed=100
R400 R401 R402 R403 R405 R406 R409 R410 R412 R413 R414 R415 R416 R417 R418 R419 R420 R421 R422 R423 R424 R425 R426 R427 R428 R429 R430 R431: "RES, 10.0 k, 1%, 0.1 W, 0603", Manufacturer="Vishay Draloric", Power_W=0.1, Supplier Part Number 1=541-1784-1-ND, TempCo="100 ppm/C", Tolerance_%=1, Value1=1%, Value2=0.1W, Value_Code=10k0, ValueDisplayed=10.0k
R408: library part CMP-0022769-5, "RES, 120, 1%, 0.1 W, 0603", Manufacturer=Yageo, Power_W=100mW, Supplier Part Number 1=311-120HRCT-ND, TempCo="100 ppm/C", Tolerance_%=1%, Value2=0.1W, Value_Code=120R, ValueDisplayed=120
SGND: "Test Point, Miniature, Black, TH", Color=Black, Manufacturer=Keystone, Supplier Part Number 1=36-5001-ND
T300 T301 T302 T303: library part CMP-0055443-2, "Terminal 90A Lug", Manufacturer=Panduit, Supplier Part Number 1=CB70-14-CY-ND, Voltage_V=600V
TP300 TP301 TP302 TP303 TP304 TP305 TP306 TP307 TP308 TP309 TP310 TP311 TP312 TP313 TP314 TP315 TP316 TP317 TP318 TP319 TP320 TP321 TP322 TP323 TP324 TP325 TP326 TP327 TP328 TP329 TP330 TP331 TP332 TP333 TP334 TP335 TP336 TP337 TP338 TP339 TP340 TP341 TP342 TP343 TP344 TP345 TP346 TP347 TP348 TP349 TP350 TP351 TP352 TP353 TP354 TP355: library part 0312-0-15-15-34-27-10-0, "Pin Receptacle, .032-.046\" .075\" Dia, Gold, TH", Manufacturer=Mill-Max, Supplier Part Number 1=0312-015153427100-ND
U200: library part CMP-0097277-2, "3-V to 17-V Input, 3-A Synchronous Buck Module, QFN-FCMOD7", Manufacturer="Texas Instruments", Max Supply Voltage=17V, Min Supply Voltage=3V, Nominal Supply Current=100-400uA, Operating Temperature Range="-40°C to +125°C", Output Voltage=0.6-10V, Switching Frequency=1200/2000kHz
U201: "Capacitor-Free, 150-mA, Low-Dropout Regulator with Foldback Current Limit for Portable Devices, DBV0005A", Alternate Manufacturer="Texas Instruments"
U202: library part CMP-0093655-2, "-4-V to 110-V, Bidirectional, 1-MHz, 5V/µs, Ultra-Precise Current Sense Amplifier, SOT23-8", Input Bias Current=40uA, Input Offset Voltage=0.002mV, Manufacturer="Texas Instruments", Max Supply Voltage=20V, Min Supply Voltage=2.7V, Nominal Supply Current=2.5mA, Operating Temperature Range="-40°C to +125°C", Voltage Gain=0.1V/mV
U203: library part CMP-0093654-2, "-4-V to 110-V, Bidirectional, 1-MHz, 5V/µs, Ultra-Precise Current Sense Amplifier, SOT23-8", Input Bias Current=40uA, Input Offset Voltage=0.002mV, Manufacturer="Texas Instruments", Max Supply Voltage=20V, Min Supply Voltage=2.7V, Nominal Supply Current=2.5mA, Operating Temperature Range="-40°C to +125°C", Voltage Gain=0.05V/mV
U300: library part CMP-0066129-2, "High Side OR-ing FET Controller, DDC0006A (SOT-23-T-6)", Alternate Manufacturer="Texas Instruments"
U400 U402 U403 U404 U405: library part CMP-0047016-1, "Hex Noninverting Drivers, D0014A, TUBE", F @ Nom Voltage(Max)(Mhz)=75, Generic Part Number=SN74ALS1034, ICC @ Nom Voltage(Max)(mA)=0.014, Manufacturer="Texas Instruments", Operating Temperature Range(C)="0 to 70", Rating=Catalog, tpd @ Nom Voltage(Max)(ns)=8, Voltage(Nom)(V)=5
U401: library part CMP-0065059-3, "3.3-V to 5-V RS-485 Transceivers With +/-18-kV IEC ESD Protection, D0008A (SOIC-8)", Alternate Manufacturer="Texas Instruments", Alternate PartNumber=THVD1450DR, Operating Temperature Range="-40 to 125 C"

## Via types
v1: diameter 20, hole 10, Top Layer to Bottom Layer, 398 vias
v2: diameter 32, hole 16, Top Layer to Bottom Layer, 232 vias
v3: diameter 19.68, hole 7.87, Top Layer to Bottom Layer, 12 vias
v4: diameter 35, hole 25, Top Layer to Bottom Layer, 7 vias
v5: diameter 20, hole 10, Top Layer to Bottom Layer, tented both sides, 3 vias

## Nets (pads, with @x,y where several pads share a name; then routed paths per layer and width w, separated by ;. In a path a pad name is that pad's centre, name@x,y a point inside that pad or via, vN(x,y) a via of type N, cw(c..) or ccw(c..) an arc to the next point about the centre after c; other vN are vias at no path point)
3V3: C212.1 C400.2 J200.45 R223.2 R224.2 R225.1 R229.1 U201.5 U401.8 | length 12073.7
  Top Layer w20: R229.1@1161.42,1249.51 1161.42,1251.42 1328.64,1418.64 1551.36,1418.64 v1(1725,1245) ; U401.8@1763.22,3204.33 C400.2@1703.38,3204.33 1662.44,3204.33 1635,3176.89 1635,3100 1675,3060 1940,3060 1975,3025 1975,2590 2270,2295 2351.4,2295 2526.4,2120 v1(2614.23,2120) ; J200.45@2377.73,808.56 2482.09,808.56 v1@2490.65,800 ; U201.5@2614.23,2220.87 v1(2614.23,2120) ; R223.2@2619.34,1615.72 R224.2@2619.34,1687.2 2625,1692.86 2625,1820 2590,1855 2590,1935 2614.23,1959.23 v1(2614.23,2120)
  Signal Layer 3 w25: v1(1574.71,-2720) 2380,-2720 2599.69,-2500.31 ; v1@1725,1244.2 1812.76,1244.2 1886.24,1317.68 1886.24,1818.18 1933.06,1865 2040,1865 2245,2070 2441.51,2070 2491.51,2120 v1(2614.23,2120) 2694.7,2039.53 2694.7,-2404.67 2599.37,-2500
  Signal Layer 5 w20: v1@2488.47,800 2475.17,813.31 2475.17,1102.03 2445,1132.2 2445,1688.84 2575.68,1819.52 2575.68,1952.88 2614.23,1991.42 v1(2614.23,2120)
  other v1: 2490.17,800
5V: 5V.1 C209.1 C210.1 C213.1 C402.1 C403.2 C404.1 C405.2 C406.1 C407.2 C408.1 C409.2 C410.1 C411.2 J200.48 J200.84 J200.98 J200.112 J202.158 J202.180 J300.4 J301.4 J302.4 J303.4 J304.4 J305.4 J306.4 R220.2 U200.3 U201.1 U201.3 U400.14 U402.14 U403.14 U404.14 U405.14 | length 22064.8
  Top Layer w20: v1(2140,840.06) J200.48@2243.87,840.06 ; v1(2211.55,2721.73) 2258.8,2674.49 2258.8,2581.97 2290.67,2550.1 2335.94,2550.1 2353.29,2532.76 2353.29,2383.15 2367.07,2369.37 2455.65,2369.37 2471.4,2385.12 v1(2471.4,2418.58) 2511.42,2418.58 2539.42,2390.58 U201.3@2539.42,2329.13 ; J200.84@2243.87,1532.97 2137.97,1532.97 2101.91,1569.03 2101.91,1712.51 2142.84,1753.44 J200.98@2243.87,1753.44 2286.99,1753.44 v1(2288.55,1755) ; J200.112@2243.87,1973.91 2285.07,1973.91 v1(2288.55,1977.39) ; J202.158@2244.73,3493.6 2284.27,3493.6 v1(2285.67,3495) 2303.87,3513.2 2303.87,3522.4 2315.8,3534.33 2315.8,3819.82 v1(2295.56,3840.06) J202.180@2244.73,3840.06 ; U201.1@2614.23,2329.13 C213.1@2614.23,2446.47
  Top Layer w25: J303.4@2214.17,-904.33 2365.67,-904.33 2690,-580 2690,2449.9 2634.9,2505 5V.1@2514.67,2505
  Signal Layer 2 w20: v1(2285.67,3495) 2320,3460.67 2320,2970 2385.8,2904.2 2385.8,2679.32 2395.12,2670 2450,2670 2555,2565 2555,2478.18 2495.4,2418.58 v1(2471.4,2418.58)
  Signal Layer 3 w20: v1(2426.12,2418.58) v1(2471.4,2418.58)
  Signal Layer 3 w25: J301.4@100,-904.33 130.67,-904.33 150,-885 150,-805 ; J305.4@100,1178.35 128.35,1178.35 225,1275 875,1275 ; J300.4@804.72,-904.33 835.67,-904.33 865,-875 865,-805 ; J304.4@804.72,1178.35 833.35,1178.35 875,1220 875,1275 ; J306.4@1509.45,1178.35 1548.35,1178.35 1585,1215 1585,1275 ; J302.4@1520,-904.33 1544.33,-904.33 1560,-920 1560,-1130 1538.1,-1151.9 1435.68,-1151.9 1088.78,-805 865,-805 ; 150,-805 865,-805 ; 150,-805 15,-805 -12.15,-777.85 -12.15,1267.85 30,1310 1785,1310 1820,1345 1820,1890 2348.58,2418.58 v1(2395.12,2418.58) 2205.02,2228.49 2205.02,2180.51 1855.44,1830.93 1855.44,1330.44 1800,1275 1585,1275 ; 875,1275 1585,1275
  Bottom Layer w20: C404.1@1941.5,1198.7 1941.5,1119.96 2037.3,1024.16 2037.3,879.31 1999.92,841.94 1999.92,785.08 2013.59,771.41 U402.14@2092.28,771.41 2092.28,769.2 2158.57,769.2 ; v1(2140,840.06) 2158.57,821.48 2158.57,769.2 ; R220.2@2191.44,2701.62 v1(2211.55,2721.73) ; C411.2@2270.2,3692.58 2287.05,3709.43 C410.1@2287.05,3757.29 2287.05,3832.05 ; v1(2285.67,3495) 2317.19,3463.48 2317.19,3345.77 2332.95,3330 U405.14@2417.84,3330 ; 2306.06,1267.72 U403.14@2421.7,1267.72 ; C408.1@2386.5,2191.71 2373.62,2178.84 C409.2@2373.62,2127 2373.62,2025 ; 2395.12,2397.42 v1(2395.12,2418.58) ; 2416.49,2395 2418.9,2395 2588.78,2395 v1(2613.78,2420) ; 2420.39,775 U400.14@2452.28,775 ; U404.14@2421.7,1764.42 2392.78,1764.42 2373.62,1783.57 2373.62,2025 ; 2158.57,769.2 2187.74,769.2 2209.55,747.39 2392.39,747.39 2420,775 2394.42,800.58 2394.42,934.54 2391.94,934.54 2364.3,962.18 2342.49,962.18 2324.84,979.83 2324.84,1098.35 2340,1113.51 2340,1161.75 C402.1@2368.89,1190.64 2368.89,1193.98 2337.73,1225.14 2325.65,1225.14 2303.35,1247.44 2303.35,1323.45 2306.48,1326.59 2306.48,1330.69 2341.6,1365.8 2341.6,1421.91 2304.2,1459.31 2304.2,1480.69 2330,1506.49 2330,1613.26 2312.96,1630.3 2290,1630.3 2288.55,1631.75 C406.1@2288.55,1695.07 v1(2288.55,1755) v1(2288.55,1977.39) 2336.16,2025 2373.62,2025
  Bottom Layer w25: C408.1@2386.5,2191.71 2418.9,2224.11 2418.9,2395 C209.1@2418.9,2414.62
  other v3: 2379.53,2510.01 2399.21,2510.01 2418.9,2510.01 2379.53,2549.38 2399.21,2549.38 2418.9,2549.38
12V: 12Vs.1 C207.1 C208.1 J300.2 J301.2 J302.2 J303.2 J304.2 J305.2 J306.2 R219.2 U200.1 | length 15132.3
  Signal Layer 2 w25: J301.2@100,-854.33 414.33,-854.33 705,-1145 885,-1145 ; J305.2@100,1228.35 416.65,1228.35 725,920 850,920 ; J300.2@804.72,-854.33 854.33,-854.33 885,-885 885,-1145 ; J304.2@804.72,1228.35 831.15,1228.35 850,1209.5 850,920 ; J302.2@1509.45,-854.33 1569.33,-854.33 1595,-880 1595,-1145 ; J306.2@1509.45,1228.35 1516.65,1228.35 1570,1175 1570,945.29 1544.71,920 850,920 ; J303.2@2214.17,-854.33 2265.87,-854.33 2280,-868.46 2280,-1115 2250,-1145 1595,-1145 ; 885,-1145 1595,-1145
  Signal Layer 4 w39.37: 12Vs.1@2613.78,2894.01 12Vs.1@2621.93,2894.01
  Bottom Layer w12: R219.2@2191.44,2576.02 2160,2607.46 2160,2725 2185,2750 2295.71,2750 C208.1@2314.42,2731.3
  Bottom Layer w25: J301.2@100,-854.33 100,-822.37 -10,-712.37 -10,1295 ; J305.2@100,1228.35 100,1265 70,1295 -10,1295 ; 12Vs.1@2613.78,2894.01 12Vs.1@2613.78,2901.72 ; 12Vs.1@2620,2901.72 2625.7,2907.42 2625.7,3642.11 2625,3642.82 2625,3906.22 2556.22,3975 35,3975 -10,3930 -10,1295
  Bottom Layer w39.37: U200.1@2321.36,2626.64 2321.36,2724.35 C208.1@2314.42,2731.3 2332.28,2749.17 2332.28,2785.11 2388.98,2841.81 C207.1@2507.15,2841.81 2561.58,2841.81 12Vs.1@2613.78,2894.01
48V1: J200.42 R210.1 R216.2 | length 266.7
  Top Layer w20: R216.2@2076.5,763.52 2120.02,763.52 2137.97,745.57 J200.42@2243.87,745.57 ; v1(2076.76,740) R216.2@2076.76,763.26
  Bottom Layer w20: R210.1@2021.76,707.06 2054.7,740 v1(2076.76,740)
48V_Sense+: J200.37 R211.1 R217.2 | length 319
  Top Layer w20: J200.37@2377.73,682.58 2468.17,682.58 2515.6,730 R211.1@2563.5,730
  Bottom Layer w20: R217.2@2409.21,711.16 2428.05,730 v1(2515,730)
48VOUT1: C309.1 C310.1 C311.1 C312.1 C313.1 R203.2 R226.2 R301.1 R302.1 TP301.1 TP304.1 TP307.1 TP310.1 TP313.1 TP316.1 TP325.1 TP328.1 TP331.1 TP337.1 TP340.1 TP343.1 | length 5218.5
  Top Layer w20: v1(1816.07,651.08) 1833.37,633.77 1833.37,394.81 1842.82,385.37 2032.44,385.37 2070,347.81 2070,-780 2120,-830 2120,-1126.81 2153.19,-1160 2344.42,-1160 2401.03,-1216.61 2401.03,-2276.03 2455,-2330 2455,-2669.42 2404.42,-2720 1947.7,-2720 1940,-2712.3 v1(1940,-2575) ; R302.1@1838.66,-2575 v1(1940,-2575) ; R301.1@2038.97,-2575 v1(1940,-2575)
  Signal Layer 1 w100: TP328.1@175,-525 TP340.1@175,-369.8 ; TP331.1@879.72,-520.27 TP343.1@879.72,-369.8
  Bottom Layer w20: v1(1816.07,651.08) 1816.07,701.33 R203.2@1821.8,707.06 ; v1(1940,-2575) 1940,-2595 1962.17,-2617.17 2018.13,-2617.17 R226.2@2062.1,-2661.13
48VOUT2: C315.1 Q300.9 Q301.9 Q302.9 R204.2 R303.2 T301.1 TP334.1 TP346.1 U300.6 | length 6972
  Top Layer w20: v1@2528.84,778.12 R204.2@2562.35,778.12
  Signal Layer 2 w16: v1@2080,-3030 v1(2080,-3026.14) 2080,-2975 2070,-2965 2040,-2965 2030,-2955 2030,-2735 2045.94,-2719.06 2461.16,-2719.06 v1(2480,-2737.9) ; v1(2480,-3025) v1@2481.44,-3025
  Signal Layer 2 w100: TP334.1@1588.45,-528.45 TP346.1@1588.45,-369.8
  Signal Layer 1 w100: TP334.1@1588.45,-528.45 TP346.1@1588.45,-369.8
  Signal Layer 3 w12: T301.1@1145.25,-3070 1145.25,-2788.05 1237.59,-2695.7 1799.3,-2695.7 1836.8,-2658.2 1872.5,-2658.2 1910,-2695.7 2369.93,-2695.7 2477.82,-2587.82 2477.82,-2587.19 2670.4,-2394.6 2670.4,704.5 2599.9,775 v1(2528.84,775)
  Signal Layer 3 w20: T301.1@1161.42,-3114.17 T301.1@1257.87,-3017.72
  Signal Layer 3 w100: TP334.1@1588.45,-521.55 TP346.1@1588.45,-369.8
  Signal Layer 4 w100: TP334.1@1588.45,-523.45 TP346.1@1588.45,-369.8
  Bottom Layer w25: R303.2@2413.73,-2737.9 v1(2480,-2737.9) U300.6@2522.6,-2737.9
  other v1: 1500,-3500 1550,-3500 1600.39,-3500 1650,-3500 1700,-3500 1750,-3500 1800,-3500 1850,-3500 1900,-3500 1950,-3500 2000.39,-3500 2050,-3500 2100,-3500 2150,-3500 2200,-3500 2250,-3500 2300.37,-3500 2350.37,-3500 2400.76,-3500 2450.37,-3500 2500.37,-3500 2550.37,-3500 2600.37,-3500 2650.37,-3500 1499.53,-3450 1549.53,-3450 1599.92,-3450 1649.53,-3450 1699.53,-3450 1749.53,-3450 1799.53,-3450 1849.53,-3450 1899.53,-3450 1949.53,-3450 1999.92,-3450 2049.53,-3450 2099.53,-3450 2149.53,-3450 2199.53,-3450 2249.53,-3450 2299.9,-3450 2349.9,-3450 2400.29,-3450 2449.9,-3450 2499.9,-3450 2549.9,-3450 2599.9,-3450 2649.9,-3450 1500.27,-3400 1550.27,-3400 1600.66,-3400 1650.27,-3400 1700.27,-3400 1750.27,-3400 1800.27,-3400 1850.27,-3400 1900.27,-3400 1950.27,-3400 2000.66,-3400 2050.27,-3400 2100.27,-3400 2150.27,-3400 2200.27,-3400 2250.27,-3400 2300.64,-3400 2350.64,-3400 2401.03,-3400 2450.64,-3400 2500.64,-3400 2550.64,-3400 2600.64,-3400 2650.64,-3400 1499.8,-3350 1549.8,-3350 1600.19,-3350 1649.8,-3350 1699.8,-3350 1749.8,-3350 1799.8,-3350 1849.8,-3350 1899.8,-3350 1949.8,-3350 2000.19,-3350 2049.8,-3350 2099.8,-3350 2149.8,-3350 2199.8,-3350 2249.8,-3350 2300.17,-3350 2350.17,-3350 2400.56,-3350 2450.17,-3350 2500.17,-3350 2550.17,-3350 2600.17,-3350 2650.17,-3350
  other v2: 920.25,-3475 960.25,-3475 1000.25,-3475 1040.25,-3475 1080.25,-3475 1120.25,-3475 1170.25,-3475 1210.25,-3475 1250.25,-3475 1290.25,-3475 1330.25,-3475 1370.25,-3475 920.25,-3435 960.25,-3435 1000.25,-3435 1040.25,-3435 1080.25,-3435 1120.25,-3435 1170.25,-3435 1210.25,-3435 1250.25,-3435 1290.25,-3435 1330.25,-3435 1370.25,-3435 920.25,-3395 960.25,-3395 1000.25,-3395 1040.25,-3395 1080.25,-3395 1120.25,-3395 1170.25,-3395 1210.25,-3395 1250.25,-3395 1290.25,-3395 1330.25,-3395 1370.25,-3395 920.25,-3355 960.25,-3355 1000.25,-3355 1040.25,-3355 1080.25,-3355 1120.25,-3355 1170.25,-3355 1210.25,-3355 1250.25,-3355 1290.25,-3355 1330.25,-3355 1370.25,-3355 915.25,-2920 1375.25,-2920 915.25,-2880 1375.25,-2880 915.25,-2840 955.25,-2840 995.25,-2840 1295.25,-2840 1335.25,-2840 1375.25,-2840
485A: J400.3 R411.2 | length 303.7
  Top Layer w20: J400.3@1850.27,3635 1850.27,3469.73 1947.7,3372.3 R411.2@1947.7,3371.66
485B: J400.2 R404.2 | length 161.5
  Top Layer w20: R404.2@1750.27,3473.45 J400.2@1750.27,3635
BBU_ADD_0: J200.104
BBU_ADD_1: J200.106
BBU_ADD_2: J200.108
BBU_ADD_3: J200.110
BBU_ALERT_L: J200.89 | length 97.3
  Top Layer w20: J200.89@2377.73,1627.46 2475,1627.46
BBU_ISHARE: J200.24 J201.3 | length 3975.9
  Top Layer w20: v1(2001.4,462.1) J200.24@2243.87,462.1
  Signal Layer 2 w20: v1(1805,865.01) 1844.99,865.01 2001.4,708.6 v1(2001.4,462.1)
  Signal Layer 1 w20: v1@1804.61,865 1758.74,910.87 1758.74,1252.32 1720,1291.06 1720,1533.33 1599.92,1653.41 1599.92,3684.92 1645,3730 1725.27,3730 J201.3@1850.27,3855 ; v1@1804.81,865.2 v1(1805,865.01)
BKP_RED_L: J200.91 | length 104.8
  Top Layer w20: J200.91@2377.73,1658.95 2482.57,1658.95
BUF_PWM1H_D: J300.1 U400.2 | length 3174.1
  Signal Layer 2 w12: J300.1@754.72,-854.33 875.26,-733.8 1935,-733.8 1974.4,-694.4 1974.4,-694.22 2414.17,-254.44 2414.17,800 2364.56,849.61 2295.39,849.61 v1(2290,855)
  Bottom Layer w20: U400.2@2237.72,825 2260,825 v1(2290,855)
BUF_PWM1L_D: J300.3 U400.4 | length 3349.4
  Signal Layer 2 w12: J300.3@754.72,-904.33 725.08,-904.33 715.75,-895 715.75,-833.69 833.44,-716 1927.63,-716 1956.6,-687.03 1956.6,-686.84 2396.37,-247.07 2396.37,792.63 2357.19,831.81 2282.36,831.81 2268.2,845.97 2268.2,864.03 2290,885.83 v1(2290,910)
  Bottom Layer w20: U400.4@2237.72,925 2257.47,925 2272.47,910 v1(2290,910)
BUF_PWM2H_D: J300.9 U400.6 | length 3808.7
  Signal Layer 2 w12: J300.9@754.72,-1054.33 697.95,-997.55 697.95,-826.31 826.06,-698.2 1920.25,-698.2 1938.8,-679.65 1938.8,-679.47 2378.57,-239.7 2378.57,710.43 2315.8,773.2 2121.64,773.2 2108.87,785.97 2108.87,871.25 2130.97,893.35 2146.04,893.35 2277.68,1025 v1(2290,1025)
  Bottom Layer w20: U400.6@2237.72,1025 v1(2290,1025)
BUF_PWM2L_D: J300.11 U402.12 | length 3633.9
  Signal Layer 2 w12: J300.11@754.72,-1104.33 680.15,-1029.75 680.15,-818.94 818.69,-680.4 1912.88,-680.4 1921,-672.28 1921,-672.1 2360.77,-232.32 2360.77,703.05 2308.42,755.4 2114.27,755.4 2069.67,800 v1(2045,800)
  Bottom Layer w20: v1(2045,800) 2045,843.98 2072.43,871.41 U402.12@2092.28,871.41
BUF_PWM3H_D: J301.1 U400.8 | length 3996.6
  Signal Layer 2 w12: J301.1@50,-854.33 241.73,-662.6 1905.32,-662.6 2023.2,-544.72 2023.2,809.03 2038.71,824.54 2038.71,826.27 2123.6,911.15 2138.66,911.15 2292.51,1065 v1(2350.64,1065)
  Bottom Layer w20: v1(2350.64,1065) 2361.44,1075.8 2452.28,1075.8 U400.8@2452.28,1075
BUF_PWM3L_D: J301.3 U402.2 | length 3667.1
  Signal Layer 2 w12: J301.3@50,-904.33 40.38,-904.33 16.15,-880.1 16.15,-828.56 199.91,-644.8 1897.95,-644.8 1976.01,-566.74 1976.01,670.4 v1(1825,821.41)
  Bottom Layer w20: v1(1825,821.41) U402.2@1877.72,821.41
BUF_PWM4H_D: J301.9 U402.4 | length 3946.1
  Signal Layer 2 w12: J301.9@50,-1054.33 -1.65,-1002.68 -1.65,-821.18 192.54,-627 1890.58,-627 1958.21,-559.37 1958.21,657.37 1783.2,832.38 1783.2,879.61 v1(1825,921.41)
  Bottom Layer w20: v1(1825,921.41) U402.4@1877.72,921.41
BUF_PWM4L_D: J301.11 U402.6 | length 4114.2
  Signal Layer 2 w12: J301.11@50,-1104.33 44.33,-1104.33 -19.45,-1040.55 -19.45,-813.81 185.16,-609.2 1883.2,-609.2 1940.41,-552 1940.41,650 1765.4,825.01 1765.4,961.81 v1(1825,1021.41)
  Bottom Layer w20: v1(1825,1021.41) U402.6@1877.72,1021.41
BUF_PWM5H_D: J302.1 U400.12 | length 2516
  Signal Layer 2 w12: J302.1@1459.45,-854.33 1508.78,-805 1964.49,-805 2076.34,-693.15 2076.34,-692.97 2533.8,-235.51 2533.8,349.44 2485.37,397.86 2485.37,762.36 2515,791.99 v1@2515,843.04
  Bottom Layer w20: U400.12@2452.28,875 2490.76,875 v1@2516.15,849.61
  other v1: 2515.39,849.61
BUF_PWM5L_D: J302.3 U400.10 | length 2704.5
  Signal Layer 2 w12: J302.3@1459.45,-904.33 1449.83,-904.33 1425.6,-880.1 1425.6,-828.56 1466.96,-787.2 1957.12,-787.2 2058.54,-685.78 2058.54,-685.6 2467.77,-276.37 2467.77,390.3 2467.57,390.49 2467.57,941.94 v1(2415,994.51)
  Bottom Layer w20: v1(2415,994.51) 2434.51,975 U400.10@2452.28,975
BUF_PWM6H_D: J302.9 U402.10 | length 3306.7
  Signal Layer 2 w12: J302.9@1459.45,-1054.33 1407.8,-1002.68 1407.8,-821.18 1459.59,-769.4 1949.75,-769.4 2040.74,-678.41 2040.74,-678.22 2449.97,-269 2449.97,-129.8 2449.77,-129.61 2449.77,928.91 2393.2,985.48 2393.2,1003.54 2418.68,1029.02 2418.68,1087.35 2398.94,1107.09 2273.74,1107.09 2166.66,1000 v1(2155,1000)
  Bottom Layer w20: U402.10@2092.28,971.41 2126.41,971.41 v1(2155,1000)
